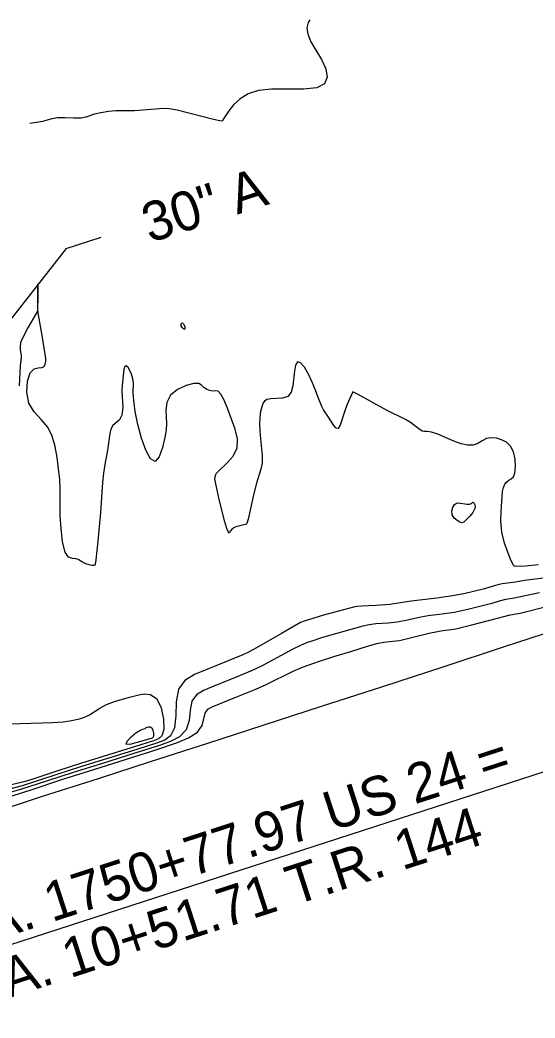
# Model space of a CAD drawing. Extents: x -468548933 to 3387700, y -306089263 to 1207014.
# Drawn here: x 1840899 to 1841391, y 537007 to 537960 of the extents above; entities that cross this region are included whole.
import ezdxf

# ---------------------------------------------------------------- set-up
doc = ezdxf.new("R2010")
doc.units = 0
for name, color, linetype in [('DT_X_Contour_Minor', 7, 'Continuous'), ('Level 14', 7, 'Continuous'), ('Level 40', 7, 'Continuous')]:
    doc.layers.add(name, color=color, linetype=linetype)

msp = doc.modelspace()

# ---------------------------------------------------------------- linework, layer by layer
at = {"layer": 'DT_X_Contour_Minor'}
for points in [[(1841175.99, 537959.67), (1841174.25, 537957.3), (1841173.08, 537952.19), (1841173.95, 537946.1), (1841176.93, 537938.92), (1841187.08, 537921.81), (1841191.19, 537913.1), (1841192.54, 537905.17), (1841189.99, 537898.81), (1841182.55, 537894.81), (1841169.9, 537893.54), (1841139.27, 537893.76), (1841126.86, 537892.23), (1841117.15, 537889.04), (1841109.48, 537884.43), (1841103.29, 537878.75), (1841098.54, 537872.99), (1841093.58, 537865.49), (1841092.32, 537863.25), (1841090.05, 537863.48), (1841084.07, 537864.8), (1841049.41, 537873.55), (1841041.89, 537874.98), (1841036.75, 537875.27), (1841008.67, 537872.93), (1840990.98, 537872.82), (1840983.92, 537872.25), (1840976.62, 537871.22), (1840970.4, 537869.84), (1840962.38, 537866.8), (1840957.64, 537865.92), (1840950.69, 537865.87), (1840942.67, 537866.17), (1840935.29, 537866.18), (1840929.77, 537865.43), (1840920.79, 537862.83), (1840915.2, 537861.73), (1840908.83, 537860.8)], [(1840949.37, 537445.76), (1840945.82, 537447.13), (1840942.56, 537452.04), (1840940.12, 537461.86), (1840938.56, 537474.41), (1840937.79, 537486.62), (1840937.68, 537496.21), (1840937.85, 537511.96), (1840937.32, 537521.14), (1840936.29, 537531.4), (1840934.87, 537542.1), (1840933.05, 537552.64), (1840930.28, 537562.51), (1840925.85, 537571.21), (1840919.52, 537578.56), (1840912.83, 537585.71), (1840907.75, 537594.09), (1840905.8, 537604.48), (1840906.59, 537614.99), (1840909.26, 537623.04), (1840912.95, 537626.87), (1840916.88, 537627.81), (1840920.23, 537628.01), (1840922.43, 537629.17), (1840923.59, 537631.28), (1840924.06, 537633.88), (1840924.07, 537636.8), (1840923.6, 537640.92), (1840920.9, 537656.71), (1840916.69, 537680.22), (1840916.39, 537683.73), (1840916.51, 537707.72), (1840916.44, 537697.51), (1840916.24, 537681.79), (1840907.32, 537666.57), (1840901.45, 537655.5), (1840900.02, 537651.6), (1840899.48, 537648.18), (1840899.65, 537644.86), (1840900.58, 537639.4), (1840900.57, 537637.6), (1840899.7, 537629.84), (1840898.72, 537610.71)], [(1841053.57, 537670.24), (1841054.02, 537670.59), (1841054.93, 537670.31), (1841055.56, 537669.68), (1841056.16, 537668.52), (1841056.63, 537666.84), (1841056.79, 537665.22), (1841056.43, 537664.42), (1841055.48, 537664.94), (1841054.3, 537666.32), (1841053.36, 537667.84), (1841053.02, 537668.95), (1841053.11, 537669.62), (1841053.57, 537670.24)], [(1841372.34, 537533.38), (1841371.99, 537540.75), (1841370.41, 537547.76), (1841367.52, 537553.08), (1841363.58, 537556.77), (1841358.97, 537559.22), (1841354.02, 537560.71), (1841349.07, 537561.14), (1841344.41, 537560.29), (1841340.23, 537558.17), (1841336.16, 537555.68), (1841331.72, 537553.97), (1841326.49, 537553.89), (1841320.37, 537555.34), (1841313.36, 537557.94), (1841298.11, 537564.4), (1841291.97, 537566.54), (1841287.95, 537567.11), (1841285.33, 537567.01), (1841283.01, 537567.48), (1841280.08, 537569.44), (1841272.06, 537575.66), (1841267.18, 537578.46), (1841249.1, 537587.32), (1841222.14, 537602.2), (1841217.11, 537604.8), (1841213.79, 537597.77), (1841211.39, 537592.21), (1841208.95, 537585.7), (1841204.95, 537573.21), (1841203.07, 537569.95), (1841201, 537570.13), (1841198.73, 537572.85), (1841193.62, 537580.67), (1841188.93, 537587.74), (1841187.31, 537590.93), (1841184.06, 537599.57), (1841181.52, 537606.34), (1841178.32, 537614.13), (1841174.67, 537621.81), (1841170.81, 537628.27), (1841167.18, 537632.48), (1841164.26, 537633.4), (1841162.41, 537630.43), (1841161.33, 537624.66), (1841159.72, 537610.6), (1841158.05, 537604.65), (1841154.89, 537600.53), (1841149.87, 537598.74), (1841138.74, 537598.31), (1841135.05, 537597.52), (1841132.78, 537596.08), (1841131.47, 537594.3), (1841130.65, 537592.42), (1841129.05, 537586.4), (1841128.51, 537583.69), (1841128.12, 537579.83), (1841128.01, 537574.46), (1841128.22, 537567.78), (1841128.8, 537560.17), (1841130.4, 537544.09), (1841130.43, 537536.95), (1841129.35, 537530.98), (1841125.08, 537517.71), (1841122.67, 537508.05), (1841117.26, 537483.39), (1841115.79, 537479.33), (1841115.28, 537478.72), (1841114.32, 537478.34), (1841109.04, 537477.15), (1841105.25, 537476.01), (1841102.08, 537474.4), (1841100.36, 537472.41), (1841099.12, 537469.99), (1841098.21, 537471.1), (1841096.76, 537474.59), (1841094.8, 537481.02), (1841089.91, 537500.87), (1841085.32, 537521.43), (1841085.87, 537525), (1841086.19, 537526), (1841086.86, 537527.16), (1841088.51, 537529.01), (1841097.17, 537537.15), (1841102.78, 537543.68), (1841106.57, 537551.42), (1841106.99, 537560.01), (1841104.79, 537569.2), (1841097.7, 537588.38), (1841094.26, 537596.81), (1841091.13, 537602.76), (1841088.36, 537605.38), (1841085.76, 537605.78), (1841083.09, 537605.57), (1841080.2, 537606.05), (1841077.32, 537607.3), (1841074.79, 537609.13), (1841072.66, 537611.2), (1841069.9, 537612.75), (1841065.21, 537612.91), (1841057.87, 537610.99)], [(1841057.87, 537610.99), (1841049.67, 537607.11), (1841042.97, 537601.57), (1841039.54, 537594.79), (1841038.63, 537587.54), (1841039.11, 537574.76), (1841038.83, 537568.73), (1841037.7, 537561.25), (1841035.51, 537551.75), (1841032.36, 537543), (1841028.45, 537538.57), (1841024.02, 537541.08), (1841019.5, 537549.25), (1841015.33, 537560.85), (1841011.94, 537573.75), (1841009.47, 537586.24), (1841008.02, 537596.71), (1841007.56, 537604.04), (1841007.6, 537613.21), (1841007, 537617.43), (1841005.86, 537621.62), (1841004.29, 537625.37), (1841002.48, 537628.23), (1841000.71, 537629.67), (1840999.32, 537629.18), (1840998.52, 537626.49), (1840996.77, 537611.08), (1840996.69, 537605.77), (1840997.43, 537589.8), (1840996.68, 537582.62), (1840994.33, 537578.1), (1840988.15, 537572.77), (1840986.18, 537569.32), (1840985.11, 537565.27), (1840982.98, 537549.38), (1840980.28, 537535.69), (1840978.96, 537527.25), (1840978.03, 537518.27), (1840976.16, 537489.83), (1840973.77, 537462.52), (1840971.81, 537444.67), (1840971.03, 537440.6), (1840970.59, 537439.62), (1840969.74, 537439.14), (1840968.07, 537439.2), (1840965.36, 537439.83), (1840962.15, 537440.91), (1840959.16, 537442.29), (1840954.91, 537445.02), (1840952.55, 537445.66), (1840949.37, 537445.76)], [(1841394.08, 537439.87), (1841381.35, 537438.58), (1841371.44, 537438.14), (1841370.25, 537439.61), (1841368.18, 537443.6), (1841365.09, 537450.92), (1841361.78, 537460.59), (1841359.26, 537471.17), (1841358.24, 537481.4), (1841358.35, 537490.71), (1841359.86, 537509.95), (1841360.68, 537513.77), (1841362.03, 537516.75), (1841363.82, 537519.02), (1841365.91, 537520.63), (1841368.12, 537521.86), (1841370.15, 537523.7), (1841371.66, 537527.3), (1841372.34, 537533.38)], [(1841332.05, 537491.04), (1841331.35, 537489.71), (1841328.67, 537486.39), (1841324.63, 537482.03), (1841322.96, 537480.62), (1841321.31, 537480.07), (1841319.19, 537480.51), (1841316.38, 537482.01), (1841313.58, 537484.43), (1841311.71, 537487.61), (1841311.44, 537491.27), (1841312.43, 537494.79), (1841314.05, 537497.47), (1841315.81, 537498.81), (1841317.79, 537499.05), (1841325.88, 537497.59), (1841328.36, 537497.66), (1841330.05, 537498.43), (1841331.15, 537499.32), (1841331.95, 537499.57), (1841332.71, 537498.66), (1841333.31, 537496.96), (1841333.57, 537495.08), (1841333.37, 537493.52), (1841332.9, 537492.37), (1841332.05, 537491.04)], [(1841401.3, 537427.55), (1841380.92, 537424.9), (1841372.09, 537423.26), (1841359.47, 537421.85), (1841355.2, 537420.76), (1841341.2, 537416.48), (1841322.89, 537412.07), (1841312.09, 537410.12), (1841297.12, 537408.09), (1841272.61, 537405.09), (1841252.27, 537402.01), (1841238.95, 537401.2), (1841225.1, 537400.48), (1841220.89, 537400.05), (1841217.48, 537399.36), (1841189.13, 537391.87), (1841170.64, 537386.24), (1841166.95, 537384.97), (1841148.8, 537374.34), (1841125.17, 537360.77), (1841117.53, 537356.67), (1841111.97, 537354.06), (1841087.77, 537344.01), (1841066.01, 537335.24), (1841056.78, 537329.59), (1841050.65, 537321.15), (1841048.43, 537309.14), (1841048.1, 537295.84), (1841046.96, 537284.27), (1841043.06, 537276.74), (1841037.62, 537272.67), (1841029.55, 537269.74), (1841011.78, 537264.07)], [(1841394.98, 537413.26), (1841369.45, 537407.75), (1841362.67, 537406.84), (1841356.48, 537405.06), (1841349.56, 537402.99), (1841326.74, 537397.29), (1841313.75, 537394.53), (1841302.09, 537392.85), (1841288.79, 537391.16), (1841281.88, 537390.03), (1841269.03, 537387.2), (1841259.27, 537385.12), (1841250.65, 537384.27), (1841238.92, 537383.48), (1841232.55, 537382.63), (1841226.4, 537381.27), (1841200.44, 537373.92), (1841188.14, 537370.44), (1841177.87, 537367.12), (1841172.82, 537365.34), (1841167.01, 537362.94), (1841159.65, 537359.36), (1841129.81, 537343.17), (1841121.02, 537338.95)], [(1840888.78, 537218.65), (1840909, 537225.02), (1840940.34, 537235.29), (1840969.96, 537244.63), (1840995.15, 537252.5), (1841026.15, 537262.53), (1841049.73, 537270.34), (1841060.26, 537274.8), (1841068.89, 537280.37), (1841073.27, 537286.71), (1841076.02, 537298.33), (1841078.7, 537302.03), (1841082.74, 537304.51), (1841105.4, 537313.61), (1841124.51, 537321.23), (1841134.45, 537325.57), (1841160.19, 537338.36), (1841169.06, 537342.11), (1841185.1, 537348.01), (1841198.79, 537352.42), (1841214.98, 537357.08), (1841231.91, 537362.49), (1841239.99, 537364.77), (1841246.41, 537366.11), (1841255.02, 537366.95), (1841258.09, 537367.21), (1841261.57, 537367.76), (1841274.17, 537370.79), (1841291.16, 537374.97), (1841302.9, 537377.09), (1841310.89, 537378.13), (1841315.41, 537378.94), (1841330.58, 537382.51), (1841362.18, 537390.76), (1841365.86, 537391.82), (1841371.04, 537392.67), (1841376.67, 537393.88), (1841404.21, 537400.76)], [(1841121.02, 537338.95), (1841105.72, 537332.59), (1841082.14, 537323.04), (1841074.37, 537319.87), (1841067.74, 537315.81), (1841063.33, 537309.74), (1841061.63, 537301.07), (1841060.69, 537291.27), (1841057.93, 537282.32), (1841051.66, 537275.77), (1841043.68, 537271.5), (1841032.38, 537267.6), (1841008.92, 537260.04), (1840978.09, 537250.39), (1840950.31, 537241.74), (1840925.68, 537233.7), (1840900.06, 537225.37), (1840882.12, 537220.37)], [(1840875.44, 537288.29), (1840899.51, 537288.64), (1840930.53, 537289.48), (1840940.59, 537290.17), (1840946.91, 537291.01), (1840956.14, 537293.05), (1840960.91, 537294.51), (1840965.67, 537296.65), (1840975.63, 537303.13), (1840981.97, 537306.59), (1840989.71, 537309.58), (1841003.84, 537313.65), (1841012.87, 537315.96), (1841017.9, 537316.78), (1841024.07, 537316.12), (1841029.9, 537312.01), (1841034.15, 537303.34), (1841036.43, 537292.5), (1841036.57, 537282.78), (1841034.63, 537276.69), (1841031.59, 537273.7), (1841026.73, 537271.88), (1841014.64, 537268.1), (1840992.21, 537261.18), (1840957.12, 537250.45), (1840935.55, 537243.37), (1840908.68, 537234.41), (1840903.12, 537232.79), (1840884.66, 537228.34)], [(1841018.85, 537283.74), (1841019.81, 537284.66), (1841020.74, 537285.1), (1841022.14, 537285.45), (1841023.75, 537285.34), (1841025.23, 537284.31), (1841026.31, 537282.11), (1841026.89, 537279.36), (1841026.92, 537276.89), (1841026.42, 537275.34), (1841025.59, 537274.57), (1841022.48, 537273.64), (1841009.97, 537269.89), (1841004.08, 537268.59), (1841000.68, 537268.91), (1841001.58, 537271.61), (1841005.41, 537275.62), (1841010.03, 537279.42), (1841013.68, 537281.81), (1841016.18, 537282.99), (1841018.85, 537283.74)], [(1841011.78, 537264.07), (1840990.21, 537257.35), (1840958.12, 537247.48), (1840934.65, 537239.87), (1840901.59, 537229.08), (1840883.39, 537224.35)]]:
    msp.add_lwpolyline(points, dxfattribs=at)
at = {"layer": 'Level 14'}
msp.add_lwpolyline([(1840542.66, 537095.21), (1840591.58, 537111.29), (1840641.98, 537127.81), (1840693.24, 537144.55), (1840747.12, 537162.32), (1840806.94, 537181.91), (1840865.28, 537200.76), (1840919.92, 537218.8), (1840974.4, 537236), (1841023.94, 537252.15), (1841078.62, 537269.7), (1841131.48, 537286.96), (1841187.17, 537304.92), (1841245.68, 537323.72), (1841303.25, 537342.62), (1841360.61, 537361.51), (1841411.77, 537378.02)], dxfattribs=at)
at = {"layer": 'Level 40'}
for p, q in [((1840943.63, 537741.72), (1840976.93, 537752.53)), ((1840943.63, 537741.72), (1840717.66, 537455.37)), ((1840775.21, 537040.08), (1841517.68, 537281.13))]:
    msp.add_line(p, q, dxfattribs=at)

# ---------------------------------------------------------------- texts
for s, p in [('30" A', (1841023.32, 537746.76)), ('STA. 1750+77.97 US 24 =', (1840810.58, 537060.17)), ('STA. 10+51.71 T.R. 144', (1840827.95, 537006.67))]:
    msp.add_text(s, height=37.5, rotation=17.9864, dxfattribs=at).set_placement(p)

doc.saveas('drawing.dxf')
